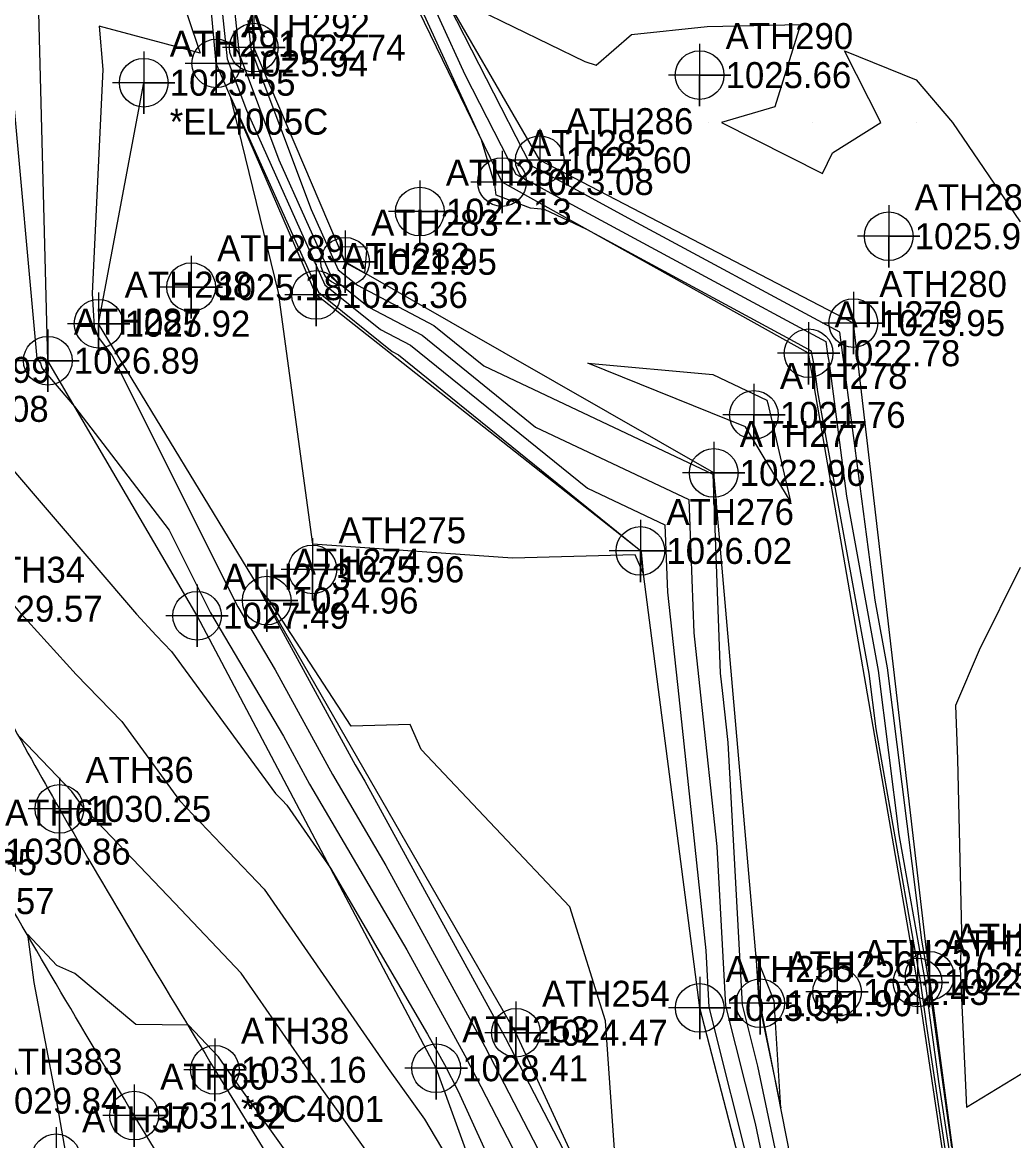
# Model space of a CAD drawing. Extents: x 1213164 to 1213550, y 766120 to 766870.
# Drawn here: x 1213354.1 to 1213449.4, y 766292.1 to 766399.6 of the extents above; entities that cross this region are included whole.
import ezdxf

# ---------------------------------------------------------------- set-up
doc = ezdxf.new("R2010")
doc.units = 0
for name, color, linetype in [('Default', 7, 'Continuous'), ('Exist DTM Breakline', 7, 'Continuous'), ('Exist DTM Breakline Cogo Comment', 7, 'Continuous'), ('Exist DTM Breakline Cogo Elevation', 7, 'Continuous'), ('Exist DTM Breakline Cogo Number', 7, 'Continuous'), ('Exist DTM Breakline Cogo Point CELL', 7, 'Continuous'), ('Exist DTM Crownline', 7, 'Continuous'), ('Exist DTM Crownline Cogo Elevation', 7, 'Continuous'), ('Exist DTM Crownline Cogo Number', 7, 'Continuous'), ('Exist DTM Crownline Cogo Point CELL', 7, 'Continuous'), ('Exist DTM Drainline Cogo Elevation', 7, 'Continuous'), ('Exist DTM Drainline Cogo Number', 7, 'Continuous'), ('Exist DTM Drainline Cogo Point CELL', 7, 'Continuous'), ('Exist DTM QL2 LIDAR Elevation Point', 7, 'Continuous'), ('Exist DTM Regular Point CELL', 7, 'Continuous'), ('Exist DTM Regular Point Cogo Comment', 7, 'Continuous'), ('Exist DTM Regular Point Cogo Elevation', 7, 'Continuous'), ('Exist DTM Regular Point Cogo Number', 7, 'Continuous'), ('Exist DTM Regular Point Underwater CELL', 7, 'Continuous'), ('Exist DTM Regular Point Underwater Cogo Elevation', 7, 'Continuous'), ('Exist DTM Regular Point Underwater Cogo Number', 7, 'Continuous'), ('Exist Hydro Stream or Body of Water', 7, 'Continuous'), ('Exist Roads EOP', 7, 'Continuous'), ('Exist Roads EOP Cogo Point CELL', 7, 'Continuous')]:
    doc.layers.add(name, color=color, linetype=linetype)

msp = doc.modelspace()

# ---------------------------------------------------------------- linework, layer by layer
at = {"layer": 'Default'}
for points in [[(1213371.26, 766419.9), (1213373.77, 766396.14), (1213375.62, 766391.21), (1213383.16, 766374.41), (1213388.51, 766370.12), (1213391.37, 766368.61), (1213408.39, 766354.84), (1213415.83, 766351.32), (1213416.08, 766344.85), (1213417.16, 766334.78), (1213419.76, 766310.39), (1213420.06, 766304.95), (1213424.27, 766288.24)], [(1213364.05, 766417.86), (1213371.18, 766396.68), (1213361.46, 766399.26), (1213361.8, 766395.12), (1213360.78, 766373.56), (1213360.98, 766370.36), (1213361.35, 766369.37), (1213362.67, 766367.65), (1213374.8, 766343.44), (1213378.38, 766337.39), (1213383.87, 766327.33), (1213389, 766318.57), (1213398.54, 766301.17), (1213406.41, 766285.96)], [(1213373.5, 766409.86), (1213374.9, 766396.62), (1213378.72, 766386.43), (1213383.8, 766375.14), (1213387.39, 766372.25), (1213392.5, 766369.55), (1213403.4, 766360.73), (1213418.13, 766353.77), (1213418.62, 766340.96), (1213419.26, 766334.95), (1213420.82, 766320.4), (1213421.65, 766305.07), (1213424.51, 766293.76), (1213426.19, 766285.79)], [(1213350.53, 766405.47), (1213351.41, 766397.98), (1213352.26, 766395.19), (1213353.06, 766393.79), (1213355.46, 766367.31), (1213355.81, 766366.88), (1213355.95, 766366.43), (1213356.14, 766366.16), (1213359.09, 766362.71), (1213368.17, 766350.82), (1213372.16, 766342.87), (1213379.17, 766331.01), (1213381.68, 766326.4), (1213391.02, 766310.47), (1213396.59, 766300.3), (1213401.19, 766291.42)], [(1213442.81, 766291.15), (1213441.02, 766303.14), (1213440.42, 766307.49), (1213436.13, 766331.72), (1213435.46, 766337.03), (1213430.53, 766364.11), (1213430.21, 766366.53), (1213429.97, 766367.81), (1213429.94, 766368.03), (1213427.93, 766369.12), (1213408.32, 766379.74), (1213404.27, 766381.66), (1213402.92, 766381.78), (1213399.63, 766383.02), (1213399.49, 766384.04), (1213398.21, 766388.35), (1213390.38, 766405.42)], [(1213391.79, 766405.17), (1213396.62, 766394.63), (1213401.51, 766385.05), (1213403.59, 766383.92), (1213404.87, 766383.23), (1213420.12, 766374.97), (1213431.3, 766368.95), (1213431.46, 766367.73), (1213431.62, 766366.88), (1213433.29, 766354.09), (1213436.35, 766337.31), (1213438.33, 766321.56), (1213440.79, 766307.7), (1213442.15, 766297.8), (1213443.12, 766291.32)], [(1213443.43, 766291.5), (1213443.29, 766292.46), (1213441.15, 766307.9), (1213440.54, 766311.4), (1213437.24, 766337.59), (1213436.06, 766344.08), (1213433.02, 766367.24), (1213432.94, 766367.64), (1213432.65, 766369.86), (1213412.32, 766380.82), (1213406.37, 766384.04), (1213403.73, 766385.47), (1213402.95, 766385.89), (1213394.44, 766402.58), (1213408.13, 766395.88), (1213409.23, 766395.54), (1213412.61, 766398.46), (1213419.89, 766399.25), (1213428.87, 766399.43), (1213426.41, 766391.52), (1213421.27, 766390), (1213431, 766385.1), (1213431.94, 766387.11), (1213436.58, 766390), (1213433.11, 766396.89), (1213440, 766394.11), (1213443.49, 766390), (1213450, 766380.45)], [(1213323.04, 766401.29), (1213323.99, 766397.94), (1213325.67, 766392.35), (1213326.8, 766389.18), (1213329.42, 766383.4), (1213329.86, 766382.37), (1213332.88, 766377.14), (1213335.62, 766372.35), (1213335.74, 766371.05), (1213342.56, 766362.65), (1213345.41, 766353.78), (1213349.18, 766348.33), (1213353.68, 766343.08), (1213359.26, 766336.95), (1213363.62, 766332.42), (1213369.17, 766324.84), (1213373.89, 766319.9), (1213377.31, 766316.31), (1213389.25, 766299.05), (1213392.73, 766294.19), (1213400.2, 766281.6)], [(1213337.36, 766400.83), (1213340.93, 766389.02), (1213344.34, 766383.07), (1213345.6, 766369.18), (1213349.19, 766364.77), (1213350.68, 766360.11), (1213352.66, 766357.24), (1213365.05, 766342.75), (1213366.94, 766340.68), (1213368.42, 766339.15), (1213378.42, 766325.5), (1213379.05, 766324.85), (1213379.5, 766324.37), (1213383.69, 766318.32), (1213393.03, 766302.36), (1213394.64, 766299.43), (1213395.96, 766296.87), (1213404.69, 766277.75)], [(1213375.74, 766399.82), (1213376.03, 766397.1), (1213381.83, 766381.66), (1213384.43, 766375.86), (1213386.28, 766374.38), (1213393.62, 766370.49), (1213398.42, 766366.61), (1213420.43, 766356.21), (1213421.16, 766337.07), (1213421.37, 766335.12), (1213421.87, 766330.4), (1213423.25, 766305.19), (1213424.74, 766299.28), (1213427.56, 766285.88)], [(1213389.63, 766367.99), (1213390.24, 766367.67), (1213413.37, 766348.96), (1213413.53, 766348.88), (1213413.54, 766348.73), (1213413.76, 766346.68), (1213412.98, 766348.45), (1213401.19, 766348.13), (1213382.89, 766349.41), (1213381.99, 766349.47), (1213378.69, 766373.66), (1213374.11, 766392.43), (1213382.53, 766373.69), (1213389.63, 766367.99)], [(1213387.22, 766378.05), (1213384.5, 766378.02), (1213384.93, 766376.88), (1213385.06, 766376.58), (1213385.16, 766376.51), (1213386.99, 766375.54), (1213387.22, 766378.05)], [(1213408.44, 766366.88), (1213420.43, 766365.79), (1213425.65, 766363.32), (1213425.72, 766363), (1213427.92, 766353.58), (1213423.6, 766360.76), (1213408.44, 766366.88)], [(1213450, 766347.23), (1213446.05, 766339.28), (1213443.78, 766333.96), (1213443.96, 766328.8), (1213444.36, 766312.22), (1213444.21, 766308.65), (1213444.83, 766295.35), (1213454.41, 766301.17)], [(1213410.14, 766303.65), (1213406.71, 766314.59), (1213392.41, 766329.73), (1213391.36, 766332.12), (1213385.67, 766331.97), (1213377.74, 766344.17), (1213376.85, 766345.21), (1213377.45, 766344.02), (1213377.59, 766343.78), (1213386.05, 766328.27), (1213386.98, 766326.67), (1213400.49, 766302.03), (1213411.64, 766280.51), (1213411.65, 766280.47), (1213411.66, 766280.44), (1213411.77, 766280.25), (1213411.98, 766280.11), (1213411.81, 766280.54), (1213411.74, 766280.72), (1213410.14, 766303.65)], [(1213390.85, 766285.97), (1213381.51, 766299), (1213375.11, 766308.24), (1213368.73, 766314.95), (1213359.93, 766324.18), (1213358.83, 766325.69), (1213353.75, 766330.97)], [(1213388.98, 766277.75), (1213373.78, 766298.94), (1213372.92, 766300.18), (1213370.03, 766303.22), (1213364.97, 766303.28), (1213359.11, 766308.18), (1213357.4, 766308.96), (1213354.57, 766311.98), (1213355.16, 766307.33), (1213357.33, 766296.07), (1213358.22, 766290.92)], [(1213426.98, 766295.28), (1213426.34, 766305.53), (1213424.59, 766309.99), (1213424.85, 766305.32), (1213424.98, 766304.8), (1213426.98, 766295.28)]]:
    msp.add_lwpolyline(points, dxfattribs=at)
at = {"layer": 'Exist DTM Breakline'}
for points in [[(1213458.36, 766304.67), (1213456.15, 766280.48), (1213457.95, 766246.9), (1213447.47, 766261.8), (1213441.28, 766307.97), (1213433.95, 766370.73), (1213403.81, 766386.39), (1213393.08, 766404.94), (1213391.08, 766440.45), (1213383.54, 766456.52), (1213369.39, 766482.2), (1213351.86, 766502.12)], [(1213525.39, 766207.47), (1213482.01, 766225.05), (1213449.3, 766226.19), (1213431.7, 766256.62), (1213419.18, 766304.88), (1213413.48, 766348.82), (1213382.31, 766373.43), (1213372.71, 766395.69), (1213369.18, 766434.58), (1213366.95, 766449.61), (1213359.43, 766466.81), (1213345.1, 766468.72)], [(1213448.72, 766182.98), (1213435.67, 766212.97), (1213412.22, 766248.51), (1213393.85, 766299.08), (1213370.87, 766342.59), (1213356.52, 766367.11), (1213355.51, 766406.8)], [(1213468.09, 766192.57), (1213448.63, 766213.66), (1213442.08, 766219.96), (1213424.22, 766253.24), (1213401.52, 766302.49), (1213377.56, 766344.05), (1213361.4, 766370.67), (1213365.74, 766393.84)]]:
    msp.add_lwpolyline(points, dxfattribs=at)
at = {"layer": 'Exist DTM Breakline Cogo Point CELL'}
for points in [[(1213372.71, 766398.69), (1213372.71, 766392.69), (1213372.71, 766395.69), (1213375.71, 766395.69), (1213369.71, 766395.69)], [(1213365.74, 766396.84), (1213365.74, 766390.84), (1213365.74, 766393.84), (1213368.74, 766393.84), (1213362.74, 766393.84)], [(1213403.81, 766389.39), (1213403.81, 766383.39), (1213403.81, 766386.39), (1213406.81, 766386.39), (1213400.81, 766386.39)], [(1213382.31, 766376.43), (1213382.31, 766370.43), (1213382.31, 766373.43), (1213385.31, 766373.43), (1213379.31, 766373.43)], [(1213361.4, 766373.67), (1213361.4, 766367.67), (1213361.4, 766370.67), (1213364.4, 766370.67), (1213358.4, 766370.67)], [(1213433.95, 766373.73), (1213433.95, 766367.73), (1213433.95, 766370.73), (1213436.95, 766370.73), (1213430.95, 766370.73)], [(1213356.52, 766370.11), (1213356.52, 766364.11), (1213356.52, 766367.11), (1213359.52, 766367.11), (1213353.52, 766367.11)], [(1213413.48, 766351.82), (1213413.48, 766345.82), (1213413.48, 766348.82), (1213416.48, 766348.82), (1213410.48, 766348.82)], [(1213377.56, 766347.05), (1213377.56, 766341.05), (1213377.56, 766344.05), (1213380.56, 766344.05), (1213374.56, 766344.05)], [(1213370.87, 766345.59), (1213370.87, 766339.59), (1213370.87, 766342.59), (1213373.87, 766342.59), (1213367.87, 766342.59)], [(1213441.28, 766310.97), (1213441.28, 766304.97), (1213441.28, 766307.97), (1213444.28, 766307.97), (1213438.28, 766307.97)], [(1213419.18, 766307.88), (1213419.18, 766301.88), (1213419.18, 766304.88), (1213422.18, 766304.88), (1213416.18, 766304.88)], [(1213401.52, 766305.49), (1213401.52, 766299.49), (1213401.52, 766302.49), (1213404.52, 766302.49), (1213398.52, 766302.49)], [(1213393.85, 766302.08), (1213393.85, 766296.08), (1213393.85, 766299.08), (1213396.85, 766299.08), (1213390.85, 766299.08)]]:
    msp.add_lwpolyline(points, dxfattribs=at)
for centre in [(1213372.71, 766395.69), (1213365.74, 766393.84), (1213403.81, 766386.39), (1213382.31, 766373.43), (1213361.4, 766370.67), (1213433.95, 766370.73), (1213356.52, 766367.11), (1213413.48, 766348.82), (1213377.56, 766344.05), (1213370.87, 766342.59), (1213441.28, 766307.97), (1213419.18, 766304.88), (1213401.52, 766302.49), (1213393.85, 766299.08)]:
    msp.add_circle(centre, 2.34, dxfattribs=at)
at = {"layer": 'Exist DTM Crownline'}
msp.add_lwpolyline([(1213408.83, 766222.6), (1213398.45, 766239.79), (1213380.35, 766269.07), (1213364.82, 766294.53)], dxfattribs=at)
msp.add_spline([(1213364.82, 766294.53), (1213349.91, 766319.91), (1213339.18, 766339.49), (1213331.7, 766355.27), (1213321.98, 766382.66), (1213317.52, 766424.05), (1213319.57, 766440.21), (1213325.28, 766470.16)], degree=3, dxfattribs=at)
at = {"layer": 'Exist DTM Crownline Cogo Point CELL'}
msp.add_lwpolyline([(1213364.82, 766297.53), (1213364.82, 766291.53), (1213364.82, 766294.53), (1213367.82, 766294.53), (1213361.82, 766294.53)], dxfattribs=at)
msp.add_circle((1213364.82, 766294.53), 2.34, dxfattribs=at)
at = {"layer": 'Exist DTM Drainline Cogo Point CELL'}
for points in [[(1213376.32, 766400.22), (1213376.32, 766394.22), (1213376.32, 766397.22), (1213379.32, 766397.22), (1213373.32, 766397.22)], [(1213400.18, 766387.29), (1213400.18, 766381.29), (1213400.18, 766384.29), (1213403.18, 766384.29), (1213397.18, 766384.29)], [(1213385.1, 766379.62), (1213385.1, 766373.62), (1213385.1, 766376.62), (1213388.1, 766376.62), (1213382.1, 766376.62)], [(1213429.65, 766370.83), (1213429.65, 766364.83), (1213429.65, 766367.83), (1213432.65, 766367.83), (1213426.65, 766367.83)], [(1213420.53, 766359.32), (1213420.53, 766353.32), (1213420.53, 766356.32), (1213423.53, 766356.32), (1213417.53, 766356.32)], [(1213440.13, 766310.33), (1213440.13, 766304.33), (1213440.13, 766307.33), (1213443.13, 766307.33), (1213437.13, 766307.33)], [(1213425, 766308.33), (1213425, 766302.33), (1213425, 766305.33), (1213428, 766305.33), (1213422, 766305.33)]]:
    msp.add_lwpolyline(points, dxfattribs=at)
for centre in [(1213376.32, 766397.22), (1213400.18, 766384.29), (1213385.1, 766376.62), (1213429.65, 766367.83), (1213420.53, 766356.32), (1213440.13, 766307.33), (1213425, 766305.33)]:
    msp.add_circle(centre, 2.34, dxfattribs=at)
at = {"layer": 'Exist DTM QL2 LIDAR Elevation Point'}
for p, q in [((1213420, 766390), (1213420, 766390)), ((1213430, 766390), (1213430, 766390)), ((1213440, 766390), (1213440, 766390))]:
    msp.add_line(p, q, dxfattribs=at)
at = {"layer": 'Exist DTM Regular Point CELL'}
for points in [[(1213419.17, 766397.57), (1213419.17, 766391.57), (1213419.17, 766394.57), (1213422.17, 766394.57), (1213416.17, 766394.57)], [(1213437.35, 766382.08), (1213437.35, 766376.08), (1213437.35, 766379.08), (1213440.35, 766379.08), (1213434.35, 766379.08)], [(1213370.3, 766377.18), (1213370.3, 766371.18), (1213370.3, 766374.18), (1213373.3, 766374.18), (1213367.3, 766374.18)], [(1213381.96, 766350.05), (1213381.96, 766344.05), (1213381.96, 766347.05), (1213384.96, 766347.05), (1213378.96, 766347.05)]]:
    msp.add_lwpolyline(points, dxfattribs=at)
for centre in [(1213419.17, 766394.57), (1213437.35, 766379.08), (1213370.3, 766374.18), (1213381.96, 766347.05)]:
    msp.add_circle(centre, 2.34, dxfattribs=at)
at = {"layer": 'Exist DTM Regular Point Underwater CELL'}
for points in [[(1213392.28, 766384.44), (1213392.28, 766378.44), (1213392.28, 766381.44), (1213395.28, 766381.44), (1213389.28, 766381.44)], [(1213424.39, 766364.9), (1213424.39, 766358.9), (1213424.39, 766361.9), (1213427.39, 766361.9), (1213421.39, 766361.9)], [(1213432.39, 766309.42), (1213432.39, 766303.42), (1213432.39, 766306.42), (1213435.39, 766306.42), (1213429.39, 766306.42)]]:
    msp.add_lwpolyline(points, dxfattribs=at)
for centre in [(1213392.28, 766381.44), (1213424.39, 766361.9), (1213432.39, 766306.42)]:
    msp.add_circle(centre, 2.34, dxfattribs=at)
at = {"layer": 'Exist Hydro Stream or Body of Water'}
for points in [[(1213462.58, 766303.68), (1213457.24, 766280.72), (1213458.54, 766244.27), (1213446.98, 766261.33), (1213440.13, 766307.33), (1213429.65, 766367.83), (1213400.18, 766384.29), (1213389.88, 766405.51), (1213387.13, 766439.71), (1213382.82, 766456.43), (1213368.02, 766480.63), (1213349.52, 766498.12), (1213324.24, 766505.78)], [(1213528.18, 766208.95), (1213518.13, 766232.16), (1213482.65, 766228.64), (1213450.6, 766228.86), (1213434.62, 766256.54), (1213425, 766305.33), (1213420.53, 766356.32), (1213385.1, 766376.62), (1213376.32, 766397.22), (1213374.29, 766436.33), (1213371.57, 766451.85), (1213360.53, 766468.46), (1213342.81, 766469.47)]]:
    msp.add_lwpolyline(points, dxfattribs=at)
at = {"layer": 'Exist Roads EOP'}
msp.add_line((1213372.58, 766298.93), (1213388.06, 766273.76), dxfattribs=at)
msp.add_spline([(1213331.54, 766460.38), (1213328.2, 766439.13), (1213326.88, 766418.06), (1213328.89, 766392), (1213339.56, 766359.27), (1213347.2, 766343.26), (1213357.64, 766324.02), (1213372.58, 766298.93)], degree=3, dxfattribs=at)
at = {"layer": 'Exist Roads EOP Cogo Point CELL'}
for points in [[(1213357.64, 766327.02), (1213357.64, 766321.02), (1213357.64, 766324.02), (1213360.64, 766324.02), (1213354.64, 766324.02)], [(1213372.58, 766301.93), (1213372.58, 766295.93), (1213372.58, 766298.93), (1213375.58, 766298.93), (1213369.58, 766298.93)], [(1213357.31, 766293.43), (1213357.31, 766287.43), (1213357.31, 766290.43), (1213360.31, 766290.43), (1213354.31, 766290.43)]]:
    msp.add_lwpolyline(points, dxfattribs=at)
for centre in [(1213357.64, 766324.02), (1213372.58, 766298.93), (1213357.31, 766290.43)]:
    msp.add_circle(centre, 2.34, dxfattribs=at)

# ---------------------------------------------------------------- texts
at = {"layer": 'Exist DTM Breakline Cogo Comment'}
msp.add_text('*EL4005C', height=2.5, dxfattribs=at).set_placement((1213368.24, 766388.84))
at = {"layer": 'Exist DTM Breakline Cogo Elevation'}
for s, p in [('1025.94', (1213375.21, 766394.44)), ('1025.55', (1213368.24, 766392.59)), ('1025.60', (1213406.31, 766385.14)), ('1026.36', (1213384.81, 766372.18)), ('1025.92', (1213363.9, 766369.42)), ('1025.95', (1213436.45, 766369.48)), ('1026.89', (1213359.02, 766365.86)), ('1026.02', (1213415.98, 766347.57)), ('1024.96', (1213380.06, 766342.8)), ('1027.49', (1213373.37, 766341.34)), ('1025.34', (1213443.78, 766306.72)), ('1025.55', (1213421.68, 766303.63)), ('1024.47', (1213404.02, 766301.24)), ('1028.41', (1213396.35, 766297.83)), ('1029.84', (1213351.41, 766294.72))]:
    msp.add_text(s, height=2.5, dxfattribs=at).set_placement(p)
at = {"layer": 'Exist DTM Breakline Cogo Number'}
for s, p in [('ATH292', (1213375.21, 766398.19)), ('ATH291', (1213368.24, 766396.34)), ('ATH286', (1213406.31, 766388.89)), ('ATH282', (1213384.81, 766375.93)), ('ATH288', (1213363.9, 766373.17)), ('ATH280', (1213436.45, 766373.23)), ('ATH287', (1213359.02, 766369.61)), ('ATH276', (1213415.98, 766351.32)), ('ATH274', (1213380.06, 766346.55)), ('ATH273', (1213373.37, 766345.09)), ('ATH259', (1213443.78, 766310.47)), ('ATH255', (1213421.68, 766307.38)), ('ATH254', (1213404.02, 766304.99)), ('ATH253', (1213396.35, 766301.58)), ('ATH383', (1213351.41, 766298.47))]:
    msp.add_text(s, height=2.5, dxfattribs=at).set_placement(p)
at = {"layer": 'Exist DTM Crownline Cogo Elevation'}
for s, p in [('1030.86', (1213352.41, 766318.66)), ('1031.32', (1213367.32, 766293.28))]:
    msp.add_text(s, height=2.5, dxfattribs=at).set_placement(p)
at = {"layer": 'Exist DTM Crownline Cogo Number'}
for s, p in [('ATH61', (1213352.41, 766322.41)), ('ATH60', (1213367.32, 766297.03))]:
    msp.add_text(s, height=2.5, dxfattribs=at).set_placement(p)
at = {"layer": 'Exist DTM Drainline Cogo Elevation'}
for s, p in [('1022.74', (1213378.82, 766395.97)), ('1023.08', (1213402.68, 766383.04)), ('1021.95', (1213387.6, 766375.37)), ('1022.78', (1213432.15, 766366.58)), ('1022.96', (1213423.03, 766355.07)), ('1022.22', (1213442.63, 766306.08)), ('1021.90', (1213427.5, 766304.08))]:
    msp.add_text(s, height=2.5, dxfattribs=at).set_placement(p)
at = {"layer": 'Exist DTM Drainline Cogo Number'}
for s, p in [('ATH285', (1213402.68, 766386.79)), ('ATH283', (1213387.6, 766379.12)), ('ATH279', (1213432.15, 766370.33)), ('ATH277', (1213423.03, 766358.82)), ('ATH258', (1213442.63, 766309.83)), ('ATH256', (1213427.5, 766307.83))]:
    msp.add_text(s, height=2.5, dxfattribs=at).set_placement(p)
at = {"layer": 'Exist DTM Regular Point Cogo Comment'}
msp.add_text('*OC4001', height=2.5, dxfattribs=at).set_placement((1213375.08, 766293.93))
at = {"layer": 'Exist DTM Regular Point Cogo Elevation'}
for s, p in [('1025.66', (1213421.67, 766393.32)), ('1025.90', (1213439.85, 766377.83)), ('1025.18', (1213372.8, 766372.93)), ('1029.08', (1213344.52, 766361.23)), ('1025.96', (1213384.46, 766345.8)), ('1029.57', (1213349.7, 766342.01)), ('1030.25', (1213360.14, 766322.77)), ('1030.57', (1213345.08, 766313.9)), ('1031.16', (1213375.08, 766297.68))]:
    msp.add_text(s, height=2.5, dxfattribs=at).set_placement(p)
at = {"layer": 'Exist DTM Regular Point Cogo Number'}
for s, p in [('ATH290', (1213421.67, 766397.07)), ('ATH281', (1213439.85, 766381.58)), ('ATH289', (1213372.8, 766376.68)), ('ATH299', (1213344.52, 766364.98)), ('ATH275', (1213384.46, 766349.55)), ('ATH34', (1213349.7, 766345.76)), ('ATH36', (1213360.14, 766326.52)), ('ATH35', (1213345.08, 766317.65)), ('ATH38', (1213375.08, 766301.43)), ('ATH37', (1213359.81, 766292.93))]:
    msp.add_text(s, height=2.5, dxfattribs=at).set_placement(p)
at = {"layer": 'Exist DTM Regular Point Underwater Cogo Elevation'}
for s, p in [('1022.13', (1213394.78, 766380.19)), ('1021.76', (1213426.89, 766360.65)), ('1022.43', (1213434.89, 766305.17))]:
    msp.add_text(s, height=2.5, dxfattribs=at).set_placement(p)
at = {"layer": 'Exist DTM Regular Point Underwater Cogo Number'}
for s, p in [('ATH284', (1213394.78, 766383.94)), ('ATH278', (1213426.89, 766364.4)), ('ATH257', (1213434.89, 766308.92))]:
    msp.add_text(s, height=2.5, dxfattribs=at).set_placement(p)

doc.saveas('drawing.dxf')
